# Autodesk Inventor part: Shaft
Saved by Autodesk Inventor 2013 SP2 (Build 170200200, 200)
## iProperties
Created: 2020-02
Part Number: Shaft
Material: Steel
Document SubType Name: Modeling
Designer: DELL
Density: 1 g/cm^3
CustomPartVersion: 1
Author: DELL
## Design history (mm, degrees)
sketch "Main Sketch"
  geometry: L1 (0, 0)-(20, 0) reference; L2 (0, 0)-(0, 2.6); L3 (20, 2.6)-(20, 0); L4 (0, 2.6)-(20, 2.6)
  constraints: 8 end point, 2 horizontal, 2 vertical
  dimensions: "d3" = 5.2 diameter of L4 L1 (derived)
revolve "Revolution1" sketch "Main Sketch" stored, may be unused: angle "d4" = 0 deg
chamfer "Chamfer1" distance "d5" = 0.25; stored, may be unused: second distance "d6" = 0.125, angle "d7" = 45 deg
chamfer "Chamfer2" distance "d8" = 0.25; stored, may be unused: second distance "d9" = 0.125, angle "d10" = 45 deg
node "Involute Splining1"
body "Solid1"
feature "Shaft Groove"
other parameters: "d0" = 0, "d1" = 0, "d2" = 0
